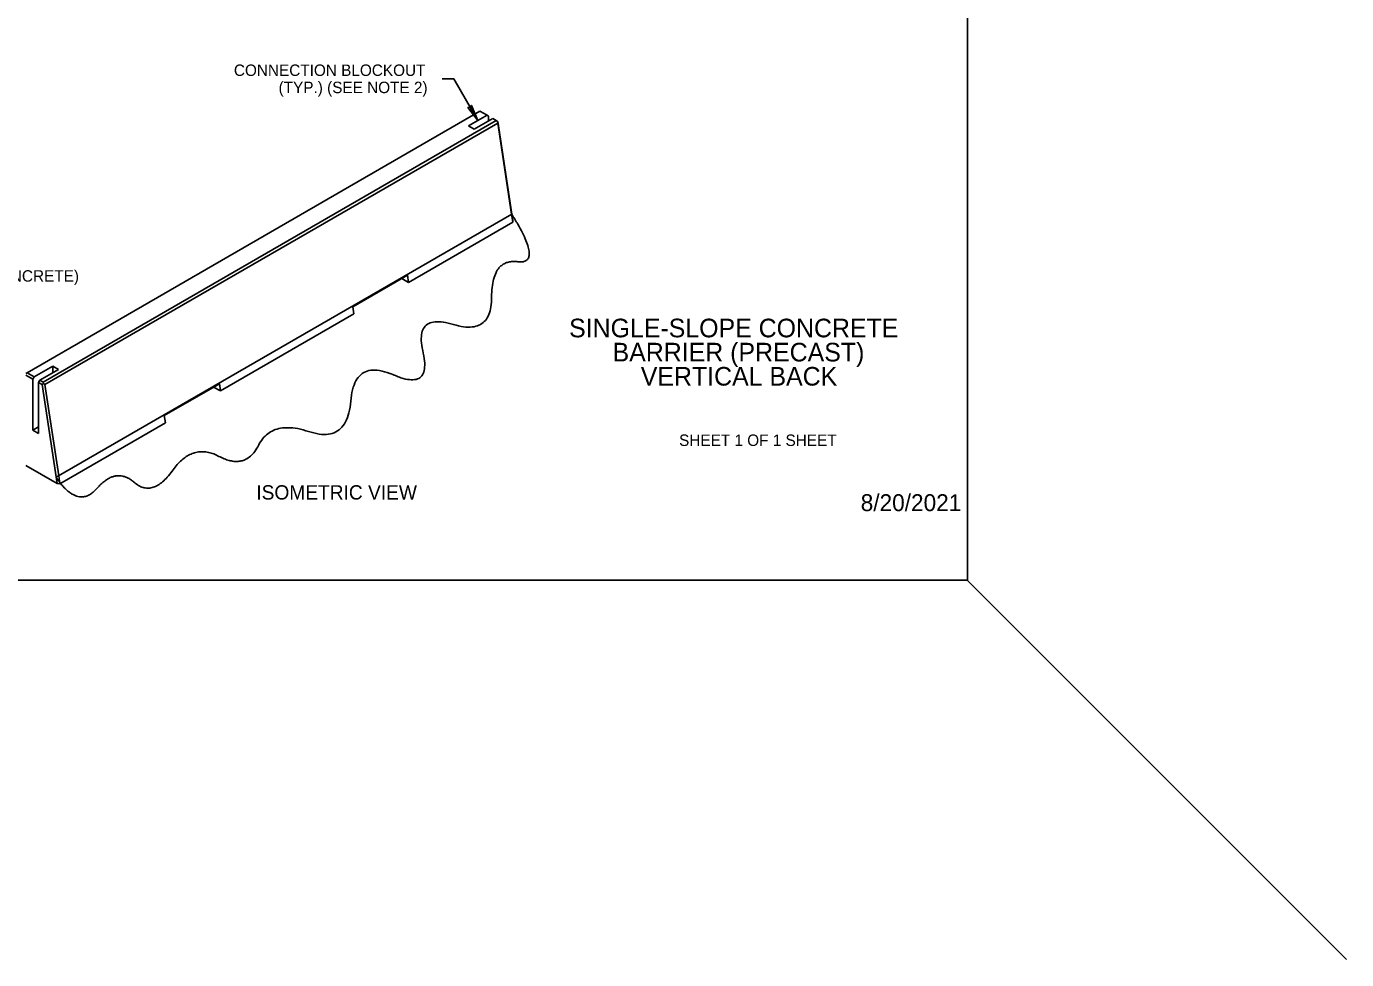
# Model space of a CAD drawing. Extents: x 99862 to 103680, y 99470 to 102076.
# Drawn here: x 101837 to 103680, y 99470 to 100773 of the extents above; entities that cross this region are included whole.
import ezdxf

# ---------------------------------------------------------------- set-up
doc = ezdxf.new("R2010")
doc.units = 0
for name, color, linetype in [('Level 1', 7, 'Continuous'), ('Level 15', 7, 'Continuous'), ('Level 2', 7, 'Continuous'), ('Level 20', 7, 'Continuous'), ('Level 6', 7, 'Continuous'), ('Level 62', 7, 'Continuous')]:
    doc.layers.add(name, color=color, linetype=linetype)

msp = doc.modelspace()

# ---------------------------------------------------------------- linework, layer by layer
at = {"layer": 'Level 1'}
msp.add_line((103150, 100000), (103680.3, 99469.7), dxfattribs=at)
msp.add_lwpolyline([(99862, 99999.5), (103151, 99999.5), (103151, 102075.5), (99862, 102075.5)], close=True, dxfattribs=at)
at = {"layer": 'Level 15'}
for p in [(102417.5, 100699.4), (102467.2, 100641.1)]:
    msp.add_line(p, (102433.5, 100699.4), dxfattribs=at)
msp.add_lwpolyline([(102467.2, 100641.1), (102453.2, 100659.3), (102456.3, 100659.9), (102458.3, 100662.3)], close=True, dxfattribs=at)
at = {"layer": 'Level 2'}
for p, q in [((102470.1, 100654.3), (101837.7, 100289.1)), ((102454.2, 100633.6), (102480.1, 100648.5)), ((102488, 100643.9), (102462.2, 100629)), ((102480.1, 100648.5), (102470.1, 100654.3)), ((102480.1, 100648.5), (102482.1, 100647.4)), ((102482.1, 100640.5), (102482.1, 100647.4)), ((102492.7, 100641.3), (102488, 100643.9)), ((101860.3, 100276.1), (102492.7, 100641.3)), ((102495, 100637.6), (101862.6, 100272.5)), ((102462.2, 100629), (102454.2, 100633.6)), ((102494.8, 100640), (102492.7, 100641.3)), ((102494.8, 100640), (102495, 100639.9)), ((102495, 100637.6), (102494.8, 100640)), ((102495, 100639.9), (102514.5, 100510.5)), ((102514.2, 100510.3), (102495, 100637.6)), ((102370.2, 100415.2), (102515.9, 100499.3)), ((102515.9, 100499.3), (102514.2, 100510.3)), ((102514.5, 100510.5), (102515.8, 100501.6)), ((102515.9, 100499.3), (102515.8, 100501.6)), ((102292.5, 100381.2), (102368.7, 100425.2)), ((102368.7, 100425.2), (102370.2, 100415.2)), ((102360.8, 100420.6), (102370.2, 100415.2)), ((102107.7, 100263.6), (102294, 100371.2)), ((102292.5, 100381.2), (102294, 100371.2)), ((101847.7, 100283.4), (101873.5, 100298.3)), ((101881.5, 100293.7), (101855.6, 100278.8)), ((101873.5, 100289.1), (101873.5, 100298.3)), ((101873.5, 100298.3), (101881.5, 100293.7)), ((101835.7, 100288), (101837.7, 100289.1)), ((101845.7, 100280), (101835.7, 100285.7)), ((101837.7, 100289.1), (101847.7, 100283.4)), ((101847.7, 100283.4), (101845.7, 100280)), ((101845.7, 100208.8), (101845.7, 100280)), ((101853.6, 100275.4), (101855.6, 100278.8)), ((101853.6, 100204.2), (101853.6, 100275.4)), ((101858.6, 100272.5), (101853.6, 100275.4)), ((101855.6, 100278.8), (101860.3, 100276.1)), ((101858.6, 100272.5), (101860.5, 100273.8)), ((101860.3, 100276.1), (101860.5, 100273.8)), ((101862.6, 100272.5), (101860.5, 100273.8)), ((102029.3, 100229.3), (102106.2, 100273.6)), ((102106.2, 100273.6), (102107.7, 100263.6)), ((101879.5, 100134.2), (101858.6, 100272.5)), ((101862.6, 100272.5), (101881.8, 100145.1)), ((102098.2, 100269.1), (102107.7, 100263.6)), ((101883.5, 100134.1), (102030.8, 100219.2)), ((102029.3, 100229.3), (102030.8, 100219.2)), ((101845.7, 100208.8), (101853.6, 100213.4)), ((101853.6, 100204.2), (101845.7, 100208.8)), ((101879.5, 100134.2), (101835.7, 100159.4)), ((101881.8, 100145.1), (101883.5, 100134.1)), ((101883.5, 100134.1), (101879.5, 100134.2))]:
    msp.add_line(p, q, dxfattribs=at)
at = {"layer": 'Level 6'}
msp.add_line((102514.5, 100510.5), (101878.1, 100143.1), dxfattribs=at)
msp.add_lwpolyline([(102514.5, 100510.5), (101878.1, 100143.1)], dxfattribs=at)
msp.add_open_spline([(101878.1, 100143.1), (101909, 100097.4), (101961.9, 100158.1), (102013, 100113.7), (102069, 100191.9), (102143.1, 100152.4), (102179.3, 100224), (102284.7, 100189.4), (102294.6, 100309.6), (102403.3, 100262.7), (102377.8, 100373), (102486.4, 100340.1), (102486.4, 100448.4), (102558.9, 100439.7), (102514.5, 100510.5)], degree=2, dxfattribs=at)

# ---------------------------------------------------------------- texts
at = {"layer": 'Level 15'}
msp.add_text('8/20/2021', height=23.62, dxfattribs=at).set_placement((103001.8, 100095.8))
at = {"layer": 'Level 20'}
for s, height, p in [('CONNECTION BLOCKOUT', 16, (102126.5, 100703.4)), ('(TYP.) (SEE NOTE 2)', 16, (102188.9, 100679.4)), ('3" MIN. (ASPHALT OR CONCRETE)', 16, (101557.8, 100416.2)), ('ISOMETRIC VIEW', 20, (102157.8, 100112))]:
    msp.add_text(s, height=height, dxfattribs=at).set_placement(p)
at = {"layer": 'Level 62'}
for s, height, p in [('SINGLE-SLOPE CONCRETE', 26, (102594.6, 100338.5)), ('BARRIER (PRECAST)', 26, (102655.3, 100304.8)), ('VERTICAL BACK', 26, (102694.7, 100271.1)), ('SHEET 1 OF 1 SHEET', 16, (102748.2, 100186.8))]:
    msp.add_text(s, height=height, dxfattribs=at).set_placement(p)

doc.saveas('drawing.dxf')
